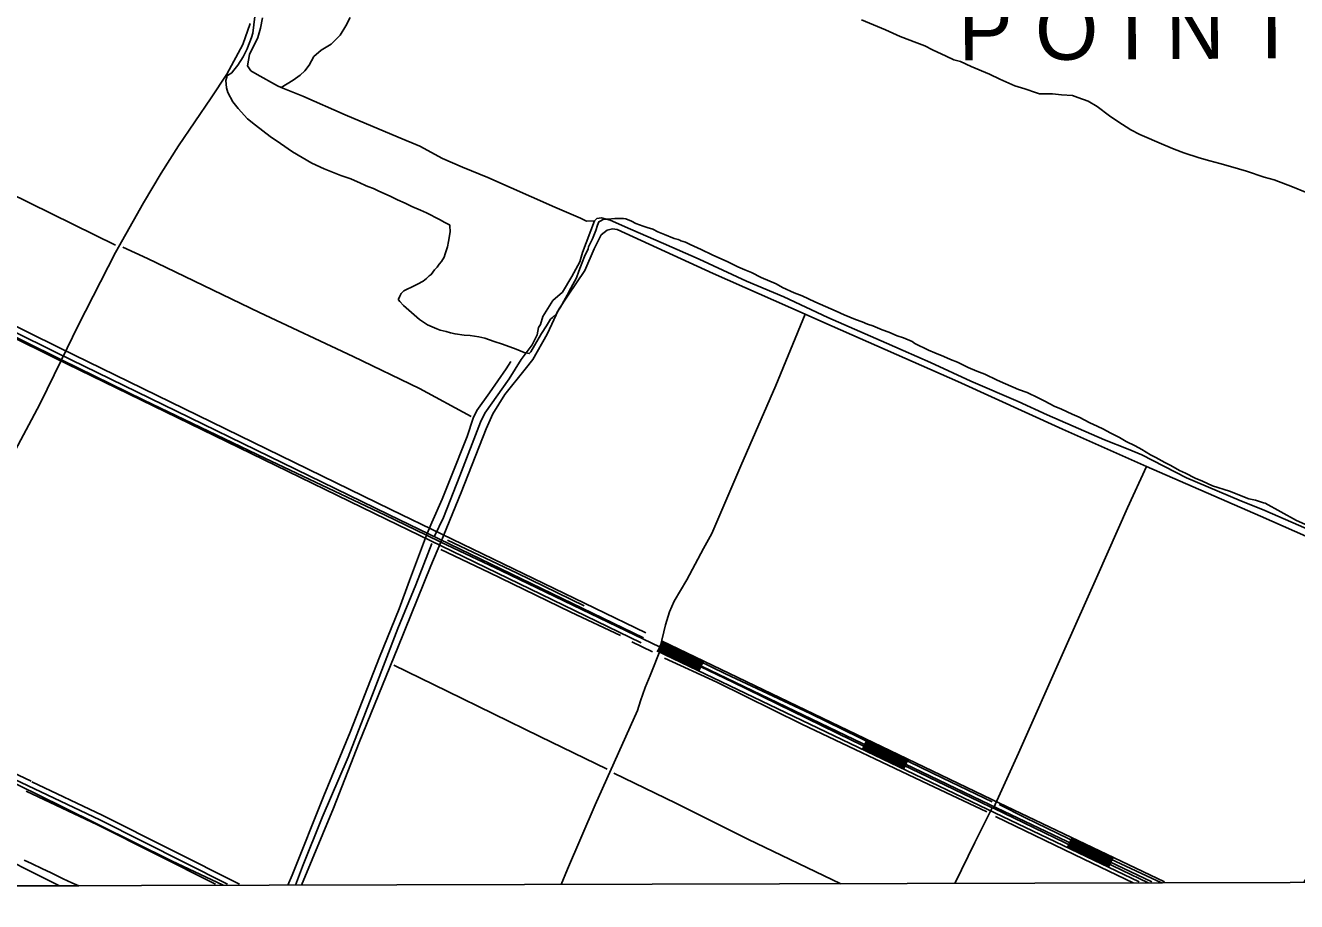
# Model space of a CAD drawing. Extents: x 3355724 to 3393621, y 594744 to 620174.
# Drawn here: x 3376384 to 3379882, y 600128 to 602539 of the extents above; entities that cross this region are included whole.
import ezdxf

# ---------------------------------------------------------------- set-up
doc = ezdxf.new("R2010")
doc.units = 0
for name, color, linetype in [('V-DTCH-CNTR', 7, 'Continuous'), ('V-GRID-FRAM', 7, 'Continuous'), ('V-ROAD-CNTR', 7, 'Continuous'), ('V-SITE-VEGE', 7, 'Continuous'), ('V-TOPO-GNAM-IDEN', 7, 'Continuous'), ('V-TOPO-SHOR', 7, 'Continuous')]:
    doc.layers.add(name, color=color, linetype=linetype)

msp = doc.modelspace()

# ---------------------------------------------------------------- linework, layer by layer
at = {"layer": 'V-DTCH-CNTR'}
for points in [[(3377002.2, 602543.9), (3376982.7, 602486.3), (3376938.3, 602404.5), (3376895, 602340.2), (3376805.1, 602207.4), (3376757.9, 602132.6), (3376709.3, 602050.8), (3376632, 601914.7), (3376529, 601713.8), (3376483.6, 601619.1), (3376423.6, 601497.2), (3376309.6, 601285)], [(3379469.3, 601325.1), (3379237.7, 601428.3), (3378949.7, 601559.5), (3378581.5, 601721.8), (3378530.2, 601744.4), (3378276.7, 601856.3), (3378012.6, 601977.3), (3378000, 601979.3), (3377985.3, 601975.6), (3377968, 601962.7), (3377948.9, 601924), (3377923.8, 601864.9), (3377877.9, 601797.1), (3377851.1, 601756.1), (3377819.8, 601689.2), (3377780.2, 601620.1), (3377758.8, 601593.2), (3377703.1, 601523.2), (3377670.2, 601470.3), (3377651.9, 601429.4), (3377582.8, 601254.2), (3377527.6, 601117.7)], [(3379474.2, 600179.9), (3379329.1, 600249.6), (3379047.7, 600385.1), (3379044.6, 600386.6), (3379010.8, 600402.8), (3378657.2, 600573), (3378331, 600731.7), (3378133.6, 600826.9), (3378130.8, 600828.2), (3378037.3, 600873.3), (3377694.2, 601038.1), (3377527.6, 601117.7), (3377487.8, 601136.7), (3377373.8, 601191.2), (3377042.7, 601348.5), (3376709.6, 601508.4), (3376483.6, 601619.1), (3376375.6, 601671.9), (3375940.5, 601885.9)], [(3378130.8, 600828.2), (3378145.4, 600890), (3378156.1, 600925.8), (3378169.7, 600955.4), (3378203.9, 601014), (3378249.6, 601100), (3378272.9, 601141.6), (3378284.4, 601166.9), (3378317, 601243.6), (3378353, 601327.4), (3378449.4, 601548.4), (3378530.2, 601744.4)], [(3377487.8, 601136.7), (3377502.1, 601171.2), (3377530.6, 601236), (3377552.9, 601290.9), (3377599.7, 601408.4), (3377616.5, 601458.3), (3377626, 601479.4), (3377661, 601528.2), (3377707, 601593.9), (3377719.4, 601614.3)], [(3379469.3, 601325.1), (3379417, 601211.7), (3379335.4, 601027.9), (3379241, 600815.3), (3379116.7, 600536.5), (3379047.7, 600385.1)], [(3379902.1, 600181), (3379961.9, 600283.8), (3380067.2, 600468.5), (3380136.3, 600583.5), (3380215.7, 600721.1), (3380347.8, 600937), (3380086.6, 601054.6), (3379782.5, 601189), (3379469.3, 601325.1)], [(3377487.8, 601136.7), (3377440.5, 601011.5), (3377412.2, 600934.2), (3377358.7, 600801.2), (3377277.5, 600595), (3377205.6, 600419.8), (3377117.6, 600201), (3377106.4, 600173.7)], [(3377527.6, 601117.7), (3377499.8, 601052.3), (3377409.1, 600827.1), (3377302.7, 600566), (3377231.6, 600385.2), (3377143.8, 600173.8)], [(3377858.6, 600175.6), (3377876.2, 600217.3), (3377951.5, 600394.7), (3378068.4, 600654.5), (3378077.1, 600680.5), (3378089.9, 600717), (3378103.5, 600750.8), (3378133.6, 600826.9)], [(3375968.4, 600642.4), (3376131.1, 600563.4), (3376484.1, 600390.4), (3376785.6, 600240.5), (3376928.2, 600173.2)], [(3379044.6, 600386.6), (3378996.9, 600290.7), (3378941.8, 600178.5)]]:
    msp.add_lwpolyline(points, dxfattribs=at)
at = {"layer": 'V-GRID-FRAM'}
msp.add_lwpolyline([(3359807.6, 618312.1), (3391397.2, 618394.8), (3391452.7, 600211.2), (3359847.2, 600128.5), (3359807.6, 618312.1)], dxfattribs=at)
at = {"layer": 'V-ROAD-CNTR'}
for p, q in [((3378124.3, 600817.5), (3378137.3, 600844.5)), ((3378237, 600763.4), (3378250, 600790.4)), ((3378687.8, 600547), (3378700.7, 600574.1)), ((3378800.4, 600492.9), (3378813.4, 600520)), ((3379251.5, 600277.2), (3379264.4, 600304.3)), ((3379364.4, 600223.4), (3379377.3, 600250.5))]:
    msp.add_line(p, q, dxfattribs=at)
for points in [[(3378078.5, 600840.8), (3377376.7, 601180.2), (3376465.9, 601623.9), (3375562.7, 602071), (3374730.4, 602478.2)], [(3378085.1, 600854.3), (3377383.3, 601193.7), (3376472.5, 601637.4), (3375569.4, 602084.5), (3374737, 602491.6)], [(3378091.6, 600867.8), (3377389.8, 601207.2), (3376479.2, 601650.8), (3375576, 602097.9), (3374743.6, 602505.1)], [(3376940.2, 600176.3), (3376588.6, 600353), (3375921, 600669.5), (3375125.5, 601062.3), (3374171.7, 601539.2)], [(3376399.3, 600459.4), (3375927.5, 600683), (3375311, 600987.4)], [(3379484.1, 600183), (3379037.5, 600395.8), (3378128.4, 600832.2)], [(3378242.2, 600774.2), (3378129.5, 600828.3)], [(3378243.5, 600776.9), (3378130.8, 600831)], [(3378244.8, 600779.6), (3378132.1, 600833.7)], [(3378246.1, 600782.3), (3378133.4, 600836.4)], [(3378247.4, 600785), (3378134.7, 600839.1)], [(3379518.7, 600183.1), (3379044, 600409.3), (3378134.8, 600845.7)], [(3378248.7, 600787.7), (3378136, 600841.8)], [(3379449.4, 600182.9), (3379031, 600382.3), (3378121.9, 600818.7)], [(3378238.3, 600766.1), (3378125.6, 600820.2)], [(3378239.6, 600768.8), (3378126.9, 600822.9)], [(3378240.9, 600771.5), (3378128.2, 600825.6)], [(3378801.7, 600495.6), (3378689.1, 600549.7)], [(3378803, 600498.3), (3378690.4, 600552.4)], [(3378804.3, 600501.1), (3378691.7, 600555.1)], [(3378805.6, 600503.8), (3378693, 600557.8)], [(3378806.9, 600506.5), (3378694.3, 600560.6)], [(3378808.2, 600509.2), (3378695.5, 600563.3)], [(3378809.5, 600511.9), (3378696.8, 600566)], [(3378810.8, 600514.6), (3378698.1, 600568.7)], [(3378812.1, 600517.3), (3378699.4, 600571.4)], [(3376973.4, 600176.4), (3376595.2, 600366.5), (3376402, 600458.1)], [(3376907, 600176.2), (3376582, 600339.6), (3376385.9, 600432.5)], [(3379365.7, 600226.1), (3379252.8, 600279.9)], [(3379367, 600228.8), (3379254.1, 600282.6)], [(3379368.3, 600231.5), (3379255.4, 600285.3)], [(3379369.5, 600234.2), (3379256.7, 600288)], [(3379370.8, 600236.9), (3379258, 600290.7)], [(3379372.1, 600239.6), (3379259.3, 600293.4)], [(3379373.4, 600242.4), (3379260.6, 600296.1)], [(3379374.7, 600245.1), (3379261.9, 600298.8)], [(3379376, 600247.8), (3379263.2, 600301.5)]]:
    msp.add_lwpolyline(points, dxfattribs=at)
at = {"layer": 'V-SITE-VEGE'}
for p, q in [((3376380.8, 600242.6), (3376400.8, 600233.2)), ((3376400.8, 600233.2), (3376430.9, 600218.2)), ((3376430.9, 600218.2), (3376453, 600208)), ((3376453, 600208), (3376487.5, 600191.4)), ((3376531.1, 600172.2), (3376341.9, 600171.7)), ((3376487.5, 600191.4), (3376511.9, 600180.4)), ((3376511.9, 600180.4), (3376531.1, 600172.2))]:
    msp.add_line(p, q, dxfattribs=at)
for points in [[(3377632.2, 601682.1), (3377607.7, 601686.2), (3377591.8, 601687.2), (3377566.3, 601690.3), (3377553.6, 601693.4), (3377541.9, 601696.5), (3377524.9, 601700.7), (3377516.4, 601703.9), (3377490.8, 601715.4), (3377468.5, 601730.2), (3377424.8, 601768.2), (3377414.1, 601779.9), (3377410.9, 601784.1), (3377410.9, 601786.2), (3377414, 601793.7), (3377418.3, 601801.1), (3377425.7, 601808.6), (3377455.3, 601823.6), (3377462.7, 601826.8), (3377478.6, 601835.4), (3377488.1, 601842.8), (3377495.5, 601850.3), (3377500.8, 601853.5), (3377509.3, 601866.3), (3377516.7, 601873.7), (3377523, 601882.3), (3377529.3, 601889.7), (3377536.7, 601901.4), (3377538.8, 601911), (3377545.1, 601930.1), (3377548.2, 601945), (3377552.4, 601971.6), (3377552.3, 601987.5), (3377551.2, 601990.7), (3377538.4, 601997), (3377523.5, 602005.4), (3377487.4, 602023.3), (3377471.4, 602030.7), (3377446.9, 602041.2), (3377428.9, 602049.6), (3377407.6, 602059.1), (3377387.4, 602069.6), (3377356.5, 602083.3), (3377341.6, 602090.6), (3377326.7, 602095.9), (3377320.3, 602099), (3377304.4, 602106.4), (3377298, 602108.5), (3377279.9, 602116.9), (3377252.3, 602126.3), (3377206.5, 602144.2), (3377172.5, 602160), (3377119.3, 602191.6), (3377086.3, 602213.8), (3377057.5, 602233.8), (3377017, 602264.4), (3376994.7, 602282.4), (3376969.1, 602310.9), (3376955.2, 602328.9), (3376941.3, 602354.3), (3376937, 602367.1), (3376935.8, 602387.2), (3376937.9, 602396.8), (3376937.9, 602400), (3376940, 602401), (3376951.6, 602408.5), (3376953.8, 602411.7), (3376968.5, 602429.8), (3376983.3, 602452.2), (3376993.8, 602474.5), (3376994.9, 602477.7), (3377006.4, 602505.4), (3377009.6, 602518.1), (3377015.7, 602563.8)], [(3378684.8, 602554.1), (3378750.8, 602526.7), (3378791.2, 602508.9), (3378836.9, 602491), (3378859.2, 602482.6), (3378880.5, 602472.1), (3378917.8, 602454.2), (3378939, 602444.7), (3378957.1, 602439.5), (3378986.9, 602425.8), (3379036.9, 602404.8), (3379065.6, 602391.1), (3379107.1, 602373.3), (3379134.7, 602364.9), (3379166.6, 602353.4), (3379175.1, 602351.3), (3379210.2, 602350.4), (3379235.7, 602348.4), (3379265.4, 602346.4), (3379280.3, 602341.1), (3379309, 602330.6), (3379333.5, 602315.9), (3379367.6, 602290.5), (3379389.9, 602274.7), (3379426.1, 602251.5), (3379450.6, 602238.9), (3379516.6, 602210.5), (3379545.3, 602198.9), (3379571.9, 602188.4), (3379614.4, 602174.8), (3379643.1, 602166.4), (3379670.7, 602159.1), (3379700.5, 602150.8), (3379744.1, 602138.2), (3379793, 602121.4), (3379820.6, 602114.1), (3379870.6, 602095.2), (3379906.8, 602080.5)], [(3379479.9, 601357.8), (3379456.5, 601372.5), (3379438.4, 601382), (3379412.9, 601394.6), (3379394.8, 601405.2), (3379369.2, 601417.8), (3379351.1, 601428.3), (3379333.1, 601436.8), (3379312.9, 601445.2), (3379284.1, 601461), (3379265, 601469.4), (3379235.2, 601483), (3379215, 601491.5), (3379189.4, 601505.1), (3379171.3, 601514.6), (3379140.5, 601529.4), (3379117.1, 601537.7), (3379080.9, 601552.5), (3379058.6, 601563), (3379024.5, 601579.8), (3379002.2, 601588.2), (3378978.8, 601597.7), (3378949, 601612.4), (3378929.9, 601619.8), (3378911.8, 601628.2), (3378886.3, 601638.7), (3378869.2, 601646), (3378832, 601663.9), (3378824.5, 601669.2), (3378800.1, 601679.7), (3378783.1, 601684.9), (3378759.7, 601695.5), (3378741.6, 601701.7), (3378716.1, 601712.3), (3378701.2, 601717.5), (3378686.3, 601723.8), (3378668.2, 601730.1), (3378637.4, 601742.7), (3378615, 601753.2), (3378556.5, 601778.5), (3378521.4, 601795.3), (3378499.1, 601803.7), (3378467.2, 601818.4), (3378450.1, 601827.9), (3378408.6, 601845.8), (3378382, 601859.4), (3378364, 601866.8), (3378344.8, 601875.2), (3378317.2, 601888.9), (3378273.5, 601907.8), (3378243.7, 601922.6), (3378223.5, 601932), (3378212.9, 601936.2), (3378200.1, 601942.5), (3378187.4, 601946.7), (3378185.2, 601947.8), (3378179.9, 601949.9), (3378169.3, 601953), (3378142.7, 601963.5), (3378124.6, 601970.9), (3378110.8, 601978.2), (3378094.8, 601983.5), (3378084.2, 601986.6), (3378064, 601994), (3378052.3, 602000.3), (3378036.3, 602006.6), (3378030, 602007.6), (3378005.6, 602007.5), (3377986.4, 602006.4), (3377975.8, 602006.3), (3377964.2, 601999.9), (3377962.1, 601998.8), (3377957.9, 601989.3), (3377953.7, 601974.4), (3377944.2, 601952), (3377940, 601942.5), (3377933.7, 601929.7), (3377932.7, 601924.4), (3377922.1, 601903.1), (3377915.8, 601887.2), (3377907.4, 601862.7), (3377900.1, 601844.6), (3377885.3, 601815.9), (3377874.8, 601796.7), (3377861.1, 601772.2), (3377858, 601766.9), (3377847.4, 601749.9), (3377845.3, 601745.6), (3377834.7, 601735), (3377829.4, 601730.7), (3377817.8, 601712.6), (3377804.1, 601691.3), (3377785.2, 601658.3), (3377774.6, 601641.3), (3377770.4, 601636), (3377756.6, 601639.1), (3377734.2, 601648.5), (3377697, 601662.2), (3377673.6, 601669.5), (3377648.1, 601679), (3377632.2, 601682.1)], [(3380125.6, 601070), (3379881.8, 601176.5), (3379795.8, 601224.3), (3379791.6, 601225.3), (3379769.2, 601232.7), (3379751.2, 601236.8), (3379698, 601257.8), (3379651.2, 601272.5), (3379623.6, 601285.1), (3379603.4, 601293.5), (3379576.8, 601307.2), (3379559.7, 601314.6), (3379536.3, 601328.3), (3379519.3, 601336.7), (3379494.8, 601350.4), (3379479.9, 601357.8)]]:
    msp.add_lwpolyline(points, dxfattribs=at)
at = {"layer": 'V-TOPO-SHOR'}
msp.add_line((3378109.6, 600815.4), (3378052.8, 600842.9), dxfattribs=at)
for points in [[(3379922.9, 601148.1), (3379795.1, 601204.4), (3379724.1, 601232.5), (3379579.7, 601294.1), (3379456.5, 601357.6), (3379418.6, 601373.5), (3379353.9, 601399.3), (3379196.1, 601467.8), (3379116.4, 601504.4), (3378986.2, 601559.9), (3378874.8, 601611.8), (3378799.1, 601644.5), (3378753.3, 601665.1), (3378592.3, 601735.1), (3378471.5, 601792.3), (3378368.2, 601835.6), (3378237.9, 601895.9), (3378140, 601939.3), (3378049.3, 601978.1), (3377993.3, 602003.2), (3377969.6, 602009.9), (3377956.3, 602007.4), (3377950.1, 602001), (3377928.2, 602000.8), (3377911.6, 602008.4), (3377840.6, 602038.8), (3377656.7, 602120.3), (3377586.5, 602149.2), (3377532, 602172.7), (3377469.6, 602206.4), (3377409.6, 602231.5), (3377263.7, 602293.1), (3377147.7, 602344.1), (3377087.8, 602368.7), (3377077.4, 602373), (3377021.3, 602403.6), (3377003.9, 602414.3), (3376995.1, 602428.3), (3377000.2, 602459), (3377023.1, 602505.6), (3377030.6, 602531.6), (3377036.5, 602559.9)], [(3377087.8, 602368.7), (3377120.6, 602388), (3377140.1, 602402.5), (3377152.5, 602413.7), (3377164.9, 602429.6), (3377177.2, 602453.3), (3377197.4, 602470.9), (3377225.5, 602487.8), (3377250.4, 602512.6), (3377265.8, 602538), (3377277.3, 602560.9)], [(3376631.4, 601934.7), (3376516.1, 601991.2), (3376215.2, 602139.4), (3375948.8, 602268.2)], [(3377509.9, 601133.7), (3377534.3, 601185), (3377579.8, 601299.4), (3377635.9, 601447.7), (3377648.1, 601472.1), (3377715.1, 601566.4), (3377748.1, 601620.2), (3377778.2, 601660.6), (3377792.7, 601687.5), (3377796.4, 601707.9), (3377801, 601716.6), (3377807.7, 601737.9), (3377835.4, 601782.2), (3377861.8, 601805.3), (3377887.9, 601848), (3377909.3, 601888.3), (3377916.8, 601914.3), (3377950.1, 602001)], [(3377610.6, 601463), (3377468.3, 601540.3), (3377285.9, 601628.1), (3377027.8, 601749.4), (3376719.8, 601897.4), (3376651.9, 601928.7)], [(3377127, 600173.7), (3377146.3, 600225), (3377201, 600359.9), (3377271.7, 600525.6), (3377343.8, 600710.2), (3377409, 600879.7), (3377458.3, 600999.7), (3377502.3, 601114)], [(3377922, 600942.3), (3377737.2, 601032.4), (3377545.3, 601123.2)], [(3378021.9, 600860.5), (3377884.6, 600924.6), (3377660.3, 601033.7), (3377527.6, 601097.1)], [(3379044.8, 600402.7), (3378909, 600468.4), (3378725, 600556.9), (3378543.4, 600646.3), (3378310.5, 600755.3), (3378160.4, 600828.6)], [(3379029.5, 600375.1), (3378868.5, 600451.4), (3378521, 600616.9), (3378286.5, 600732.3), (3378142.8, 600798.6)], [(3377984.5, 600492.8), (3377799.7, 600582.2), (3377544.6, 600707.4), (3377397.8, 600779.2)], [(3378627.6, 600177.6), (3378372.3, 600300.3), (3378174.1, 600398.9), (3378003.5, 600481.3)], [(3375951.6, 600431.6), (3376051.1, 600383.5), (3376273.8, 600273.5), (3376461, 600180.3), (3376477.8, 600172)], [(3379510.7, 600180), (3379371, 600245.5), (3379136.4, 600359.3), (3379063.8, 600395.1)], [(3379432.4, 600179.7), (3379296.4, 600245.3), (3379053.2, 600362.8)]]:
    msp.add_lwpolyline(points, dxfattribs=at)

# ---------------------------------------------------------------- texts
at = {"layer": 'V-TOPO-GNAM-IDEN'}
msp.add_text('P O I N T', height=167, rotation=0.3574, dxfattribs=at).set_placement((3378952.1, 602442.8))

doc.saveas('drawing.dxf')
